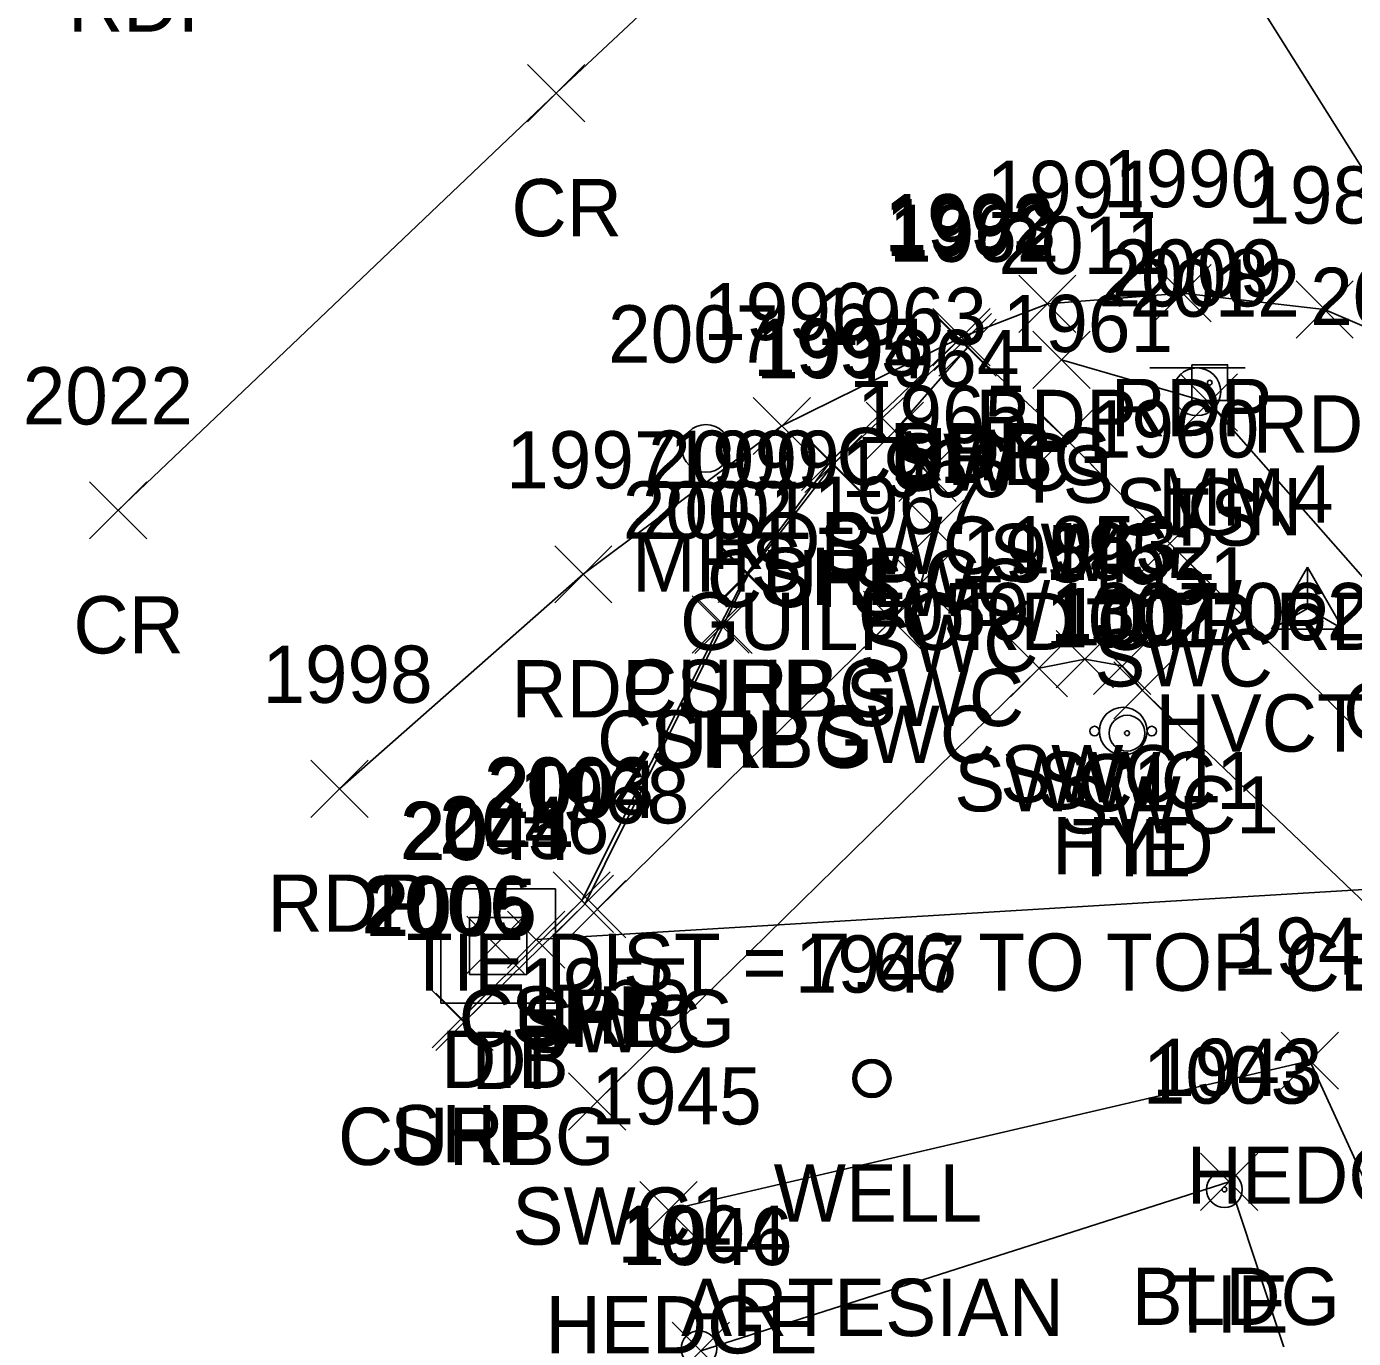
# Model space of a CAD drawing. Extents: x 1620157 to 1620595, y 115111 to 117885.
# Drawn here: x 1620161.63 to 1620208, y 115700.12 to 115745.96 of the extents above; entities that cross this region are included whole.
import ezdxf

# ---------------------------------------------------------------- set-up
doc = ezdxf.new("R2010")
doc.units = 0
for name, color, linetype in [('C_A', 7, 'Continuous'), ('C_C', 7, 'Continuous'), ('C_I', 7, 'Continuous'), ('CBP', 7, 'Continuous'), ('CPSM', 7, 'Continuous'), ('D_A', 7, 'Continuous'), ('D_I', 7, 'Continuous'), ('D_TIC', 7, 'Continuous'), ('DCP', 7, 'Continuous'), ('DS', 7, 'Continuous'), ('L_A', 7, 'Continuous'), ('L_I', 7, 'Continuous'), ('L_TIC', 7, 'Continuous'), ('LAHR', 7, 'Continuous'), ('LBC', 7, 'Continuous'), ('LELB', 7, 'Continuous'), ('P_A', 7, 'Continuous'), ('P_I', 7, 'Continuous'), ('P_TIC', 7, 'Continuous'), ('PET', 7, 'Continuous'), ('PRC', 7, 'Continuous'), ('PSP', 7, 'Continuous'), ('R_A', 7, 'Continuous'), ('R_I', 7, 'Continuous'), ('R_TIC', 7, 'Continuous'), ('RC', 7, 'Continuous'), ('RSW', 7, 'Continuous'), ('S_A', 7, 'Continuous'), ('S_C', 7, 'Continuous'), ('S_I', 7, 'Continuous'), ('SRM', 7, 'Continuous'), ('SSGN', 7, 'Continuous'), ('U_A', 7, 'Continuous'), ('U_C', 7, 'Continuous'), ('U_I', 7, 'Continuous'), ('USMH', 7, 'Continuous'), ('UWFH', 7, 'Continuous'), ('UWW', 7, 'Continuous')]:
    doc.layers.add(name, color=color, linetype=linetype)

msp = doc.modelspace()

# ---------------------------------------------------------------- linework, layer by layer
at = {"layer": 'CBP'}
for centre, radius in [((1620200.084, 115721.268), 0.625), ((1620200.084, 115721.268), 0.0833), ((1620203.486, 115705.323), 0.625), ((1620203.486, 115705.323), 0.0833), ((1620185.129, 115699.764), 0.625)]:
    msp.add_circle(centre, radius, dxfattribs=at)
at = {"layer": 'CPSM'}
for p, q in [((1620205.134, 115724.902), (1620206.384, 115727.067)), ((1620207.634, 115724.902), (1620206.384, 115727.067)), ((1620206.384, 115725.623), (1620206.384, 115727.067)), ((1620205.134, 115724.902), (1620206.384, 115725.623)), ((1620206.384, 115725.623), (1620206.384, 115725.623)), ((1620206.384, 115725.623), (1620207.634, 115724.902)), ((1620205.134, 115724.902), (1620207.634, 115724.902))]:
    msp.add_line(p, q, dxfattribs=at)
at = {"layer": 'D_TIC'}
for points in [[(1620178.437, 115713.054), (1620180.437, 115715.054)], [(1620180.437, 115713.054), (1620178.437, 115715.054)], [(1620177.018, 115712.873), (1620179.018, 115714.873)], [(1620179.018, 115712.873), (1620177.018, 115714.873)]]:
    msp.add_lwpolyline(points, dxfattribs=at)
at = {"layer": 'DCP'}
for points in [[(1620222.949, 115717.713), (1620188.216, 115772.945)], [(1620221.664, 115716.604), (1620179.437, 115714.054)]]:
    msp.add_lwpolyline(points, dxfattribs=at)
at = {"layer": 'DS'}
for p, q in [((1620176.112, 115715.831), (1620180.112, 115715.831)), ((1620176.112, 115711.831), (1620176.112, 115715.831)), ((1620180.112, 115715.831), (1620180.112, 115711.831)), ((1620177.112, 115712.831), (1620177.112, 115714.831)), ((1620177.112, 115714.831), (1620179.112, 115714.831)), ((1620179.112, 115714.831), (1620179.112, 115712.831)), ((1620178.117, 115713.833), (1620178.117, 115713.833)), ((1620178.117, 115713.833), (1620178.117, 115713.833)), ((1620179.112, 115712.831), (1620177.112, 115712.831)), ((1620180.112, 115711.831), (1620176.112, 115711.831))]:
    msp.add_line(p, q, dxfattribs=at)
at = {"layer": 'L_TIC'}
for points in [[(1620196.795, 115733.316), (1620198.795, 115735.316)], [(1620198.795, 115733.316), (1620196.795, 115735.316)], [(1620201.944, 115731.819), (1620203.944, 115733.819)], [(1620203.944, 115731.819), (1620201.944, 115733.819)], [(1620205.467, 115708.825), (1620207.467, 115710.825)], [(1620207.467, 115708.825), (1620205.467, 115710.825)], [(1620202.654, 115704.592), (1620204.654, 115706.592)], [(1620204.654, 115704.592), (1620202.654, 115706.592)], [(1620183.063, 115703.598), (1620185.063, 115705.598)], [(1620185.063, 115703.598), (1620183.063, 115705.598)], [(1620184.195, 115698.683), (1620186.195, 115700.683)], [(1620186.195, 115698.683), (1620184.195, 115700.683)]]:
    msp.add_lwpolyline(points, dxfattribs=at)
at = {"layer": 'LAHR'}
msp.add_lwpolyline([(1620213.417, 115694.681), (1620206.467, 115709.825), (1620184.063, 115704.598)], dxfattribs=at)
at = {"layer": 'LBC'}
msp.add_lwpolyline([(1620215.975, 115666.935), (1620215.066, 115670.033), (1620214.849, 115670.959), (1620214.268, 115672.742), (1620210.026, 115685.705), (1620208.37, 115691.31), (1620203.654, 115705.592), (1620185.195, 115699.683)], dxfattribs=at)
at = {"layer": 'LELB'}
msp.add_lwpolyline([(1620197.795, 115734.316), (1620202.944, 115732.819), (1620211.98, 115722.576), (1620224.178, 115708.712), (1620227.682, 115693.172), (1620232.641, 115674.457)], dxfattribs=at)
at = {"layer": 'P_TIC'}
for points in [[(1620179.141, 115742.631), (1620181.141, 115744.631)], [(1620181.141, 115742.631), (1620179.141, 115744.631)], [(1620201.022, 115735.645), (1620203.022, 115737.645)], [(1620203.022, 115735.645), (1620201.022, 115737.645)], [(1620196.3, 115735.265), (1620198.3, 115737.265)], [(1620198.3, 115735.265), (1620196.3, 115737.265)], [(1620205.988, 115735.073), (1620207.988, 115737.073)], [(1620207.988, 115735.073), (1620205.988, 115737.073)], [(1620193.298, 115734.102), (1620195.298, 115736.102)], [(1620195.298, 115734.102), (1620193.298, 115736.102)], [(1620193.298, 115734.102), (1620195.298, 115736.102)], [(1620195.298, 115734.102), (1620193.298, 115736.102)], [(1620187.021, 115731.001), (1620189.021, 115733.001)], [(1620189.021, 115731.001), (1620187.021, 115733.001)], [(1620188.711, 115729.746), (1620190.711, 115731.746)], [(1620190.711, 115729.746), (1620188.711, 115731.746)], [(1620163.836, 115728.054), (1620165.836, 115730.054)], [(1620165.836, 115728.054), (1620163.836, 115730.054)], [(1620180.085, 115725.819), (1620182.085, 115727.819)], [(1620182.085, 115725.819), (1620180.085, 115727.819)], [(1620185.796, 115725.836), (1620187.796, 115727.836)], [(1620187.796, 115725.836), (1620185.796, 115727.836)], [(1620184.884, 115724.064), (1620186.884, 115726.064)], [(1620186.884, 115724.064), (1620184.884, 115726.064)], [(1620171.564, 115718.327), (1620173.564, 115720.327)], [(1620173.564, 115718.327), (1620171.564, 115720.327)], [(1620180.029, 115714.42), (1620182.029, 115716.42)], [(1620182.029, 115714.42), (1620180.029, 115716.42)], [(1620175.807, 115710.273), (1620177.807, 115712.273)], [(1620177.807, 115710.273), (1620175.807, 115712.273)]]:
    msp.add_lwpolyline(points, dxfattribs=at)
at = {"layer": 'PET'}
msp.add_lwpolyline([(1620216.701, 115729.484), (1620211.658, 115734.07), (1620206.988, 115736.073), (1620202.022, 115736.645), (1620197.3, 115736.265), (1620194.298, 115735.102), (1620188.021, 115732.001), (1620181.085, 115726.819), (1620172.564, 115719.327)], dxfattribs=at)
at = {"layer": 'PRC'}
msp.add_lwpolyline([(1620211.93, 115771.954), (1620200.022, 115762.242), (1620180.141, 115743.631), (1620164.836, 115729.054)], dxfattribs=at)
at = {"layer": 'PSP'}
msp.add_lwpolyline([(1620194.298, 115735.102), (1620189.711, 115730.746), (1620186.796, 115726.836), (1620185.884, 115725.064), (1620181.029, 115715.42), (1620176.807, 115711.273)], dxfattribs=at)
at = {"layer": 'R_TIC'}
for points in [[(1620193.347, 115733.935), (1620195.347, 115735.935)], [(1620195.347, 115733.935), (1620193.347, 115735.935)], [(1620193.509, 115733.738), (1620195.509, 115735.738)], [(1620195.509, 115733.738), (1620193.509, 115735.738)], [(1620190.974, 115730.835), (1620192.974, 115732.835)], [(1620192.974, 115730.835), (1620190.974, 115732.835)], [(1620196.914, 115730.583), (1620198.914, 115732.583)], [(1620198.914, 115730.583), (1620196.914, 115732.583)], [(1620188.821, 115729.671), (1620190.821, 115731.671)], [(1620190.821, 115729.671), (1620188.821, 115731.671)], [(1620192.114, 115729.36), (1620194.114, 115731.36)], [(1620194.114, 115729.36), (1620192.114, 115731.36)], [(1620192.386, 115727.404), (1620194.386, 115729.404)], [(1620194.386, 115727.404), (1620192.386, 115729.404)], [(1620200.579, 115726.899), (1620202.579, 115728.899)], [(1620202.579, 115726.899), (1620200.579, 115728.899)], [(1620185.856, 115725.839), (1620187.856, 115727.839)], [(1620187.856, 115725.839), (1620185.856, 115727.839)], [(1620191.886, 115725.516), (1620193.886, 115727.516)], [(1620193.886, 115725.516), (1620191.886, 115727.516)], [(1620184.982, 115724.052), (1620186.982, 115726.052)], [(1620186.982, 115724.052), (1620184.982, 115726.052)], [(1620190.873, 115724.229), (1620192.873, 115726.229)], [(1620192.873, 115724.229), (1620190.873, 115726.229)], [(1620197.61, 115722.85), (1620199.61, 115724.85)], [(1620199.61, 115722.85), (1620197.61, 115724.85)], [(1620196.008, 115722.537), (1620198.008, 115724.537)], [(1620198.008, 115722.537), (1620196.008, 115724.537)], [(1620198.917, 115722.615), (1620200.917, 115724.615)], [(1620200.917, 115722.615), (1620198.917, 115724.615)], [(1620199.617, 115721.765), (1620201.617, 115723.765)], [(1620201.617, 115721.765), (1620199.617, 115723.765)], [(1620180.146, 115714.306), (1620182.146, 115716.306)], [(1620182.146, 115714.306), (1620180.146, 115716.306)], [(1620180.577, 115714.115), (1620182.577, 115716.115)], [(1620182.577, 115714.115), (1620180.577, 115716.115)], [(1620175.933, 115710.181), (1620177.933, 115712.181)], [(1620177.933, 115710.181), (1620175.933, 115712.181)], [(1620180.568, 115707.398), (1620182.568, 115709.398)], [(1620182.568, 115707.398), (1620180.568, 115709.398)]]:
    msp.add_lwpolyline(points, dxfattribs=at)
at = {"layer": 'RC'}
msp.add_lwpolyline([(1620194.347, 115734.935), (1620189.821, 115730.671), (1620186.856, 115726.839), (1620185.982, 115725.052), (1620181.146, 115715.306), (1620176.933, 115711.181)], dxfattribs=at)
at = {"layer": 'RSW'}
for points in [[(1620235.608, 115660.465), (1620229.313, 115680.398), (1620225.918, 115690.945), (1620221.039, 115706.713), (1620220.247, 115708.993), (1620218.98, 115710.722), (1620216.243, 115713.35), (1620201.579, 115727.899), (1620197.914, 115731.583), (1620194.509, 115734.738), (1620191.974, 115731.835), (1620193.114, 115730.36), (1620193.386, 115728.404), (1620192.886, 115726.516), (1620191.873, 115725.229), (1620181.577, 115715.115)], [(1620218.753, 115694.378), (1620220.531, 115695.011), (1620217.463, 115704.749), (1620216.711, 115706.635), (1620215.582, 115708.467), (1620200.617, 115722.765), (1620199.917, 115723.615), (1620198.61, 115723.85), (1620197.008, 115723.537), (1620181.568, 115708.398)]]:
    msp.add_lwpolyline(points, dxfattribs=at)
at = {"layer": 'SRM'}
msp.add_lwpolyline([(1620202.348, 115734.141), (1620203.598, 115734.141), (1620203.598, 115732.891), (1620202.348, 115732.891)], close=True, dxfattribs=at)
msp.add_circle((1620202.973, 115733.516), 0.0833, dxfattribs=at)
at = {"layer": 'SSGN'}
for p, q in [((1620200.878, 115734.031), (1620204.212, 115734.031)), ((1620202.525, 115733.198), (1620202.525, 115733.198))]:
    msp.add_line(p, q, dxfattribs=at)
msp.add_circle((1620202.525, 115733.198), 0.833, dxfattribs=at)
at = {"layer": 'USMH'}
for p, q in [((1620185.368, 115731.217), (1620185.368, 115731.217)), ((1620186.202, 115731.217), (1620186.202, 115731.217))]:
    msp.add_line(p, q, dxfattribs=at)
msp.add_circle((1620185.368, 115731.217), 0.833, dxfattribs=at)
at = {"layer": 'UWFH'}
msp.add_line((1620199.949, 115721.34), (1620199.949, 115721.34), dxfattribs=at)
for centre, radius in [((1620199.949, 115721.34), 0.833), ((1620198.949, 115721.34), 0.167), ((1620200.949, 115721.34), 0.167), ((1620199.949, 115720.34), 0.167)]:
    msp.add_circle(centre, radius, dxfattribs=at)
at = {"layer": 'UWW'}
for radius in [0.667, 0.625, 0.583, 0.542]:
    msp.add_circle((1620191.17, 115709.203), radius, dxfattribs=at)

# ---------------------------------------------------------------- texts
at = {"layer": 'C_A'}
for s, p in [('HVCTRL', (1620201.077, 115720.623)), ('TIE', (1620198.163, 115716.268)), ('TIE', (1620201.565, 115700.323))]:
    msp.add_text(s, height=2, dxfattribs=at).set_placement(p)
at = {"layer": 'C_C'}
msp.add_text('TIE DIST = 7.66 TO TOP CENTER', height=2, dxfattribs=at).set_placement((1620174.896, 115712.268))
at = {"layer": 'C_I'}
for s, p in [('4', (1620205.817, 115728.623)), ('1002', (1620197.234, 115724.268)), ('1003', (1620200.636, 115708.323)), ('1004', (1620182.279, 115702.764))]:
    msp.add_text(s, height=2, dxfattribs=at).set_placement(p)
at = {"layer": 'D_A'}
for s, p in [('DIB', (1620176.12, 115708.873)), ('DI', (1620177.172, 115708.833)), ('P', (1620178.815, 115709.054))]:
    msp.add_text(s, height=2, dxfattribs=at).set_placement(p)
at = {"layer": 'D_I'}
for s, p in [('2045', (1620174.679, 115716.873)), ('2044', (1620174.779, 115716.833)), ('2046', (1620176.044, 115717.054))]:
    msp.add_text(s, height=2, dxfattribs=at).set_placement(p)
at = {"layer": 'L_A'}
for s, p in [('TS', (1620196.204, 115729.316)), ('TS', (1620201.353, 115727.819)), ('HEDGE', (1620202.168, 115704.825)), ('BLDG', (1620200.245, 115700.592)), ('HEDGE', (1620179.764, 115699.598))]:
    msp.add_text(s, height=2, dxfattribs=at).set_placement(p)
at = {"layer": 'L_I'}
for s, p in [('2011', (1620195.59, 115737.316)), ('2012', (1620200.173, 115735.819)), ('2010', (1620206.484, 115735.531)), ('1944', (1620203.775, 115712.825)), ('1943', (1620200.961, 115708.592)), ('1945', (1620181.37, 115707.598)), ('1946', (1620182.448, 115702.683))]:
    msp.add_text(s, height=2, dxfattribs=at).set_placement(p)
at = {"layer": 'P_A'}
for s, p in [('RDP', (1620163.077, 115745.779)), ('CR', (1620178.574, 115738.631)), ('RDP', (1620199.51, 115731.645)), ('RDP', (1620194.788, 115731.265)), ('RDP', (1620204.476, 115731.073)), ('SHP', (1620191.834, 115730.102)), ('RDP', (1620191.786, 115730.102)), ('RDP', (1620185.509, 115727.001)), ('SHP', (1620187.246, 115725.746)), ('CR', (1620163.269, 115724.054)), ('RDP', (1620178.574, 115721.819)), ('SHP', (1620184.332, 115721.836)), ('SHP', (1620183.419, 115720.064)), ('RDP', (1620170.052, 115714.327)), ('SHP', (1620178.565, 115710.42)), ('SHP', (1620174.342, 115706.273))]:
    msp.add_text(s, height=2, dxfattribs=at).set_placement(p)
at = {"layer": 'P_I'}
for s, p in [('1990', (1620199.243, 115739.645)), ('1991', (1620195.174, 115739.265)), ('1989', (1620204.288, 115739.073)), ('1992', (1620191.605, 115738.102)), ('1992', (1620191.605, 115738.102)), ('1996', (1620185.273, 115735.001)), ('1995', (1620187.018, 115733.746)), ('2022', (1620161.498, 115732.054)), ('1997', (1620178.393, 115729.819)), ('1999', (1620184.096, 115729.836)), ('2002', (1620182.467, 115728.064)), ('1998', (1620169.871, 115722.327)), ('2003', (1620177.612, 115718.42)), ('2006', (1620173.335, 115714.273))]:
    msp.add_text(s, height=2, dxfattribs=at).set_placement(p)
at = {"layer": 'R_A'}
for s, p in [('CURBG', (1620189.93, 115729.935)), ('SWC', (1620191.871, 115729.738)), ('SWC', (1620189.336, 115726.835)), ('SWC', (1620195.276, 115726.583)), ('CURBG', (1620185.404, 115725.671)), ('SWC', (1620190.476, 115725.36)), ('SWC', (1620190.748, 115723.404)), ('SWC', (1620198.941, 115722.899)), ('CURBG', (1620182.439, 115721.839)), ('SWC', (1620190.248, 115721.516)), ('CURBG', (1620207.63, 115721.043)), ('CURBG', (1620181.564, 115720.052)), ('SWC', (1620189.235, 115720.229)), ('SWC1', (1620194.047, 115718.537)), ('SWC1', (1620195.649, 115718.85)), ('SWC1', (1620196.957, 115718.615)), ('SWC1', (1620197.656, 115717.765)), ('CURBG', (1620176.729, 115710.306)), ('SWC', (1620178.939, 115710.115)), ('CURBG', (1620172.515, 115706.181)), ('SWC1', (1620178.608, 115703.398))]:
    msp.add_text(s, height=2, dxfattribs=at).set_placement(p)
at = {"layer": 'R_I'}
for s, p in [('1993', (1620191.654, 115737.935)), ('1962', (1620191.769, 115737.738)), ('1963', (1620189.234, 115734.835)), ('1961', (1620195.741, 115734.583)), ('1994', (1620187.128, 115733.671)), ('1964', (1620190.374, 115733.36)), ('1965', (1620190.646, 115731.404)), ('1960', (1620198.752, 115730.899)), ('2000', (1620183.352, 115729.839)), ('1966', (1620190.091, 115729.516)), ('1967', (1620189.133, 115728.229)), ('2001', (1620183.131, 115728.052)), ('1953', (1620195.917, 115726.85)), ('1954', (1620194.315, 115726.537)), ('1952', (1620197.225, 115726.615)), ('1951', (1620198.491, 115725.765)), ('2004', (1620177.729, 115718.306)), ('1968', (1620178.837, 115718.115)), ('2005', (1620173.515, 115714.181)), ('1955', (1620178.876, 115711.398))]:
    msp.add_text(s, height=2, dxfattribs=at).set_placement(p)
at = {"layer": 'S_A'}
for s, p in [('MM', (1620201.162, 115728.516)), ('SIGN', (1620199.663, 115728.178))]:
    msp.add_text(s, height=2, dxfattribs=at).set_placement(p)
at = {"layer": 'S_C'}
for s, p in [('0050/1307/0627', (1620190.706, 115724.516)), ('GUILFORD CTR RD/STOP', (1620184.466, 115724.178))]:
    msp.add_text(s, height=2, dxfattribs=at).set_placement(p)
at = {"layer": 'S_I'}
for s, p in [('2008', (1620199.088, 115736.178)), ('2009', (1620199.548, 115736.516))]:
    msp.add_text(s, height=2, dxfattribs=at).set_placement(p)
at = {"layer": 'U_A'}
for s, p in [('MHS', (1620182.786, 115726.217)), ('HYD', (1620197.469, 115716.34)), ('WELL', (1620187.737, 115704.203))]:
    msp.add_text(s, height=2, dxfattribs=at).set_placement(p)
at = {"layer": 'U_C'}
msp.add_text('ARTESIAN', height=2, dxfattribs=at).set_placement((1620184.501, 115700.203))
at = {"layer": 'U_I'}
for s, p in [('2007', (1620181.951, 115734.217)), ('1001', (1620197.666, 115724.34)), ('1947', (1620188.477, 115712.203))]:
    msp.add_text(s, height=2, dxfattribs=at).set_placement(p)

doc.saveas('drawing.dxf')
